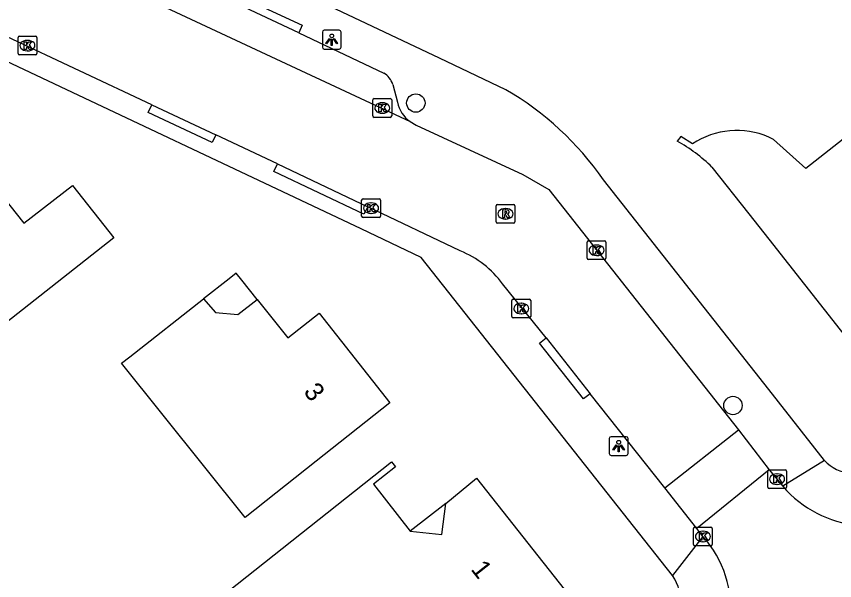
# Model space of a CAD drawing. Extents: x 159628 to 160723, y 388176 to 389416.
# Drawn here: x 159959.95 to 160003.51, y 388606.9 to 388636.95 of the extents above; entities that cross this region are included whole.
import ezdxf

# ---------------------------------------------------------------- set-up
doc = ezdxf.new("R2010")
doc.units = 0
for name, color, linetype in [('IMGEO_Boom', 7, 'Continuous'), ('IMGEO_Kolk', 7, 'Continuous'), ('IMGEO_Lichtpunt', 7, 'Continuous'), ('IMGEO_Pand', 7, 'Continuous'), ('IMGEO_Pand_nummerreeks', 7, 'Continuous'), ('IMGEO_Pand_overbouw', 7, 'Continuous'), ('IMGEO_Rijbaan_lokaal_open', 7, 'Continuous'), ('IMGEO_Rioolput', 7, 'Continuous'), ('IMGEO_Voetpad_open', 7, 'Continuous')]:
    doc.layers.add(name, color=color, linetype=linetype)

msp = doc.modelspace()

# ---------------------------------------------------------------- linework, layer by layer
at = {"layer": 'IMGEO_Boom'}
for centre in [(159981.213, 388632.329), (159998.095, 388616.223)]:
    msp.add_circle(centre, 0.489, dxfattribs=at)
at = {"layer": 'IMGEO_Kolk'}
for p, q in [((159960.038, 388634.963), (159960.038, 388635.815)), ((159960.113, 388635.889), (159960.965, 388635.889)), ((159960.526, 388635.669), (159960.551, 388635.669)), ((159961.039, 388635.815), (159961.039, 388634.963)), ((159960.549, 388635.109), (159960.524, 388635.109)), ((159960.965, 388634.889), (159960.113, 388634.889)), ((159978.927, 388631.64), (159978.927, 388632.492)), ((159979.002, 388632.566), (159979.854, 388632.566)), ((159979.928, 388632.492), (159979.928, 388631.64)), ((159979.415, 388632.346), (159979.44, 388632.346)), ((159979.854, 388631.566), (159979.002, 388631.566)), ((159979.438, 388631.786), (159979.413, 388631.786)), ((159978.404, 388627.233), (159979.256, 388627.233)), ((159978.329, 388626.307), (159978.329, 388627.159)), ((159978.817, 388627.013), (159978.842, 388627.013)), ((159979.33, 388627.159), (159979.33, 388626.307)), ((159978.84, 388626.453), (159978.815, 388626.453)), ((159979.256, 388626.233), (159978.404, 388626.233)), ((159990.334, 388624.064), (159990.334, 388624.916)), ((159990.409, 388624.99), (159991.261, 388624.99)), ((159990.822, 388624.77), (159990.847, 388624.77)), ((159991.335, 388624.916), (159991.335, 388624.064)), ((159990.845, 388624.21), (159990.82, 388624.21)), ((159991.261, 388623.99), (159990.409, 388623.99)), ((159986.326, 388620.96), (159986.326, 388621.812)), ((159986.401, 388621.886), (159987.253, 388621.886)), ((159986.814, 388621.666), (159986.839, 388621.666)), ((159987.327, 388621.812), (159987.327, 388620.96)), ((159987.253, 388620.886), (159986.401, 388620.886)), ((159986.837, 388621.106), (159986.812, 388621.106)), ((159999.943, 388611.873), (159999.943, 388612.725)), ((160000.018, 388612.799), (160000.87, 388612.799)), ((160000.431, 388612.579), (160000.456, 388612.579)), ((160000.944, 388612.725), (160000.944, 388611.873)), ((160000.454, 388612.019), (160000.429, 388612.019)), ((160000.87, 388611.799), (160000.018, 388611.799)), ((159995.994, 388608.825), (159995.994, 388609.677)), ((159996.069, 388609.751), (159996.921, 388609.751)), ((159996.482, 388609.531), (159996.507, 388609.531)), ((159996.995, 388609.677), (159996.995, 388608.825)), ((159996.505, 388608.971), (159996.48, 388608.971)), ((159996.921, 388608.751), (159996.069, 388608.751))]:
    msp.add_line(p, q, dxfattribs=at)
for points in [[(159960.038, 388634.963), (159960.038, 388635.815)], [(159960.113, 388635.889), (159960.965, 388635.889)], [(159960.359, 388635.589), (159960.482, 388635.589), (159960.482, 388635.438), (159960.612, 388635.589), (159960.776, 388635.589), (159960.63, 388635.438), (159960.783, 388635.189), (159960.631, 388635.189), (159960.546, 388635.353), (159960.482, 388635.286), (159960.482, 388635.189), (159960.359, 388635.189), (159960.359, 388635.589)], [(159961.039, 388635.815), (159961.039, 388634.963)], [(159960.965, 388634.889), (159960.113, 388634.889)], [(159978.927, 388631.64), (159978.927, 388632.492)], [(159979.002, 388632.566), (159979.854, 388632.566)], [(159979.928, 388632.492), (159979.928, 388631.64)], [(159979.248, 388632.266), (159979.371, 388632.266), (159979.371, 388632.115), (159979.501, 388632.266), (159979.665, 388632.266), (159979.519, 388632.115), (159979.672, 388631.866), (159979.52, 388631.866), (159979.435, 388632.03), (159979.371, 388631.963), (159979.371, 388631.866), (159979.248, 388631.866), (159979.248, 388632.266)], [(159979.854, 388631.566), (159979.002, 388631.566)], [(159978.404, 388627.233), (159979.256, 388627.233)], [(159978.329, 388626.307), (159978.329, 388627.159)], [(159978.65, 388626.933), (159978.773, 388626.933), (159978.773, 388626.782), (159978.903, 388626.933), (159979.067, 388626.933), (159978.921, 388626.782), (159979.074, 388626.533), (159978.922, 388626.533), (159978.837, 388626.697), (159978.773, 388626.63), (159978.773, 388626.533), (159978.65, 388626.533), (159978.65, 388626.933)], [(159979.33, 388627.159), (159979.33, 388626.307)], [(159979.256, 388626.233), (159978.404, 388626.233)], [(159990.334, 388624.064), (159990.334, 388624.916)], [(159990.409, 388624.99), (159991.261, 388624.99)], [(159990.655, 388624.69), (159990.778, 388624.69), (159990.778, 388624.539), (159990.908, 388624.69), (159991.072, 388624.69), (159990.926, 388624.539), (159991.079, 388624.29), (159990.927, 388624.29), (159990.842, 388624.454), (159990.778, 388624.387), (159990.778, 388624.29), (159990.655, 388624.29), (159990.655, 388624.69)], [(159991.335, 388624.916), (159991.335, 388624.064)], [(159991.261, 388623.99), (159990.409, 388623.99)], [(159986.326, 388620.96), (159986.326, 388621.812)], [(159986.401, 388621.886), (159987.253, 388621.886)], [(159986.647, 388621.586), (159986.77, 388621.586), (159986.77, 388621.435), (159986.9, 388621.586), (159987.064, 388621.586), (159986.918, 388621.435), (159987.071, 388621.186), (159986.919, 388621.186), (159986.834, 388621.35), (159986.77, 388621.283), (159986.77, 388621.186), (159986.647, 388621.186), (159986.647, 388621.586)], [(159987.327, 388621.812), (159987.327, 388620.96)], [(159987.253, 388620.886), (159986.401, 388620.886)], [(159999.943, 388611.873), (159999.943, 388612.725)], [(160000.018, 388612.799), (160000.87, 388612.799)], [(160000.264, 388612.499), (160000.387, 388612.499), (160000.387, 388612.348), (160000.517, 388612.499), (160000.681, 388612.499), (160000.535, 388612.348), (160000.688, 388612.099), (160000.536, 388612.099), (160000.451, 388612.263), (160000.387, 388612.196), (160000.387, 388612.099), (160000.264, 388612.099), (160000.264, 388612.499)], [(160000.944, 388612.725), (160000.944, 388611.873)], [(160000.87, 388611.799), (160000.018, 388611.799)], [(159995.994, 388608.825), (159995.994, 388609.677)], [(159996.069, 388609.751), (159996.921, 388609.751)], [(159996.315, 388609.451), (159996.438, 388609.451), (159996.438, 388609.3), (159996.568, 388609.451), (159996.732, 388609.451), (159996.586, 388609.3), (159996.739, 388609.051), (159996.587, 388609.051), (159996.502, 388609.215), (159996.438, 388609.148), (159996.438, 388609.051), (159996.315, 388609.051), (159996.315, 388609.451)], [(159996.995, 388609.677), (159996.995, 388608.825)], [(159996.921, 388608.751), (159996.069, 388608.751)]]:
    msp.add_lwpolyline(points, dxfattribs=at)
for centre, start, end in [((159960.115, 388635.813), 91.552, 178.448), ((159960.115, 388635.813), 91.552, 178.448), ((159960.963, 388635.813), 1.552, 88.448), ((159960.963, 388635.813), 1.552, 88.448), ((159960.115, 388634.965), 181.552, 268.448), ((159960.115, 388634.965), 181.552, 268.448), ((159960.963, 388634.965), 271.552, 358.448), ((159960.963, 388634.965), 271.552, 358.448), ((159979.004, 388632.49), 91.552, 178.448), ((159979.004, 388632.49), 91.552, 178.448), ((159979.852, 388632.49), 1.552, 88.448), ((159979.852, 388632.49), 1.552, 88.448), ((159979.004, 388631.642), 181.552, 268.448), ((159979.004, 388631.642), 181.552, 268.448), ((159979.852, 388631.642), 271.552, 358.448), ((159979.852, 388631.642), 271.552, 358.448), ((159978.406, 388627.157), 91.552, 178.448), ((159978.406, 388627.157), 91.552, 178.448), ((159979.254, 388627.157), 1.552, 88.448), ((159979.254, 388627.157), 1.552, 88.448), ((159978.406, 388626.309), 181.552, 268.448), ((159978.406, 388626.309), 181.552, 268.448), ((159979.254, 388626.309), 271.552, 358.448), ((159979.254, 388626.309), 271.552, 358.448), ((159990.411, 388624.914), 91.552, 178.448), ((159990.411, 388624.914), 91.552, 178.448), ((159991.259, 388624.914), 1.552, 88.448), ((159991.259, 388624.914), 1.552, 88.448), ((159990.411, 388624.066), 181.552, 268.448), ((159990.411, 388624.066), 181.552, 268.448), ((159991.259, 388624.066), 271.552, 358.448), ((159991.259, 388624.066), 271.552, 358.448), ((159986.403, 388621.81), 91.552, 178.448), ((159986.403, 388621.81), 91.552, 178.448), ((159987.251, 388621.81), 1.552, 88.448), ((159987.251, 388621.81), 1.552, 88.448), ((159986.403, 388620.962), 181.552, 268.448), ((159986.403, 388620.962), 181.552, 268.448), ((159987.251, 388620.962), 271.552, 358.448), ((159987.251, 388620.962), 271.552, 358.448), ((160000.02, 388612.723), 91.552, 178.448), ((160000.02, 388612.723), 91.552, 178.448), ((160000.868, 388612.723), 1.552, 88.448), ((160000.868, 388612.723), 1.552, 88.448), ((160000.02, 388611.875), 181.552, 268.448), ((160000.02, 388611.875), 181.552, 268.448), ((160000.868, 388611.875), 271.552, 358.448), ((160000.868, 388611.875), 271.552, 358.448), ((159996.071, 388609.675), 91.552, 178.448), ((159996.071, 388609.675), 91.552, 178.448), ((159996.919, 388609.675), 1.552, 88.448), ((159996.919, 388609.675), 1.552, 88.448), ((159996.071, 388608.827), 181.552, 268.448), ((159996.071, 388608.827), 181.552, 268.448), ((159996.919, 388608.827), 271.552, 358.448), ((159996.919, 388608.827), 271.552, 358.448)]:
    msp.add_arc(centre, 0.0765, start, end, dxfattribs=at)
for centre, major_axis, ratio, start_param, end_param in [((159960.525, 388635.389), (-0.387, 0.002), 0.722429, 4.712389, 7.853982), ((159960.55, 388635.389), (-0.39, 0.002), 0.717154, 1.570796, 4.712389), ((159979.414, 388632.066), (-0.387, 0.002), 0.722429, 4.712389, 7.853982), ((159979.439, 388632.066), (-0.39, 0.002), 0.717154, 1.570796, 4.712389), ((159978.816, 388626.733), (-0.387, 0.002), 0.722429, 4.712389, 7.853982), ((159978.841, 388626.733), (-0.39, 0.002), 0.717154, 1.570796, 4.712389), ((159990.821, 388624.49), (-0.387, 0.002), 0.722429, 4.712389, 7.853982), ((159990.846, 388624.49), (-0.39, 0.002), 0.717154, 1.570796, 4.712389), ((159986.813, 388621.386), (-0.387, 0.002), 0.722429, 4.712389, 7.853982), ((159986.838, 388621.386), (-0.39, 0.002), 0.717154, 1.570796, 4.712389), ((160000.43, 388612.299), (-0.387, 0.002), 0.722429, 4.712389, 7.853982), ((160000.455, 388612.299), (-0.39, 0.002), 0.717154, 1.570796, 4.712389), ((159996.481, 388609.251), (-0.387, 0.002), 0.722429, 4.712389, 7.853982), ((159996.506, 388609.251), (-0.39, 0.002), 0.717154, 1.570796, 4.712389)]:
    msp.add_ellipse(centre, major_axis=major_axis, ratio=ratio, start_param=start_param, end_param=end_param, dxfattribs=at)
at = {"layer": 'IMGEO_Lichtpunt'}
for p, q in [((159976.238, 388636.108), (159976.238, 388635.301)), ((159976.238, 388636.108), (159976.238, 388635.301)), ((159977.14, 388636.203), (159976.332, 388636.203)), ((159977.14, 388636.203), (159976.332, 388636.203)), ((159977.234, 388635.301), (159977.234, 388636.108)), ((159977.234, 388635.301), (159977.234, 388636.108)), ((159976.332, 388635.207), (159977.14, 388635.207)), ((159976.332, 388635.207), (159977.14, 388635.207)), ((159991.512, 388614.465), (159991.512, 388613.658)), ((159991.512, 388614.465), (159991.512, 388613.658)), ((159992.414, 388614.56), (159991.606, 388614.56)), ((159992.414, 388614.56), (159991.606, 388614.56)), ((159992.508, 388613.658), (159992.508, 388614.465)), ((159992.508, 388613.658), (159992.508, 388614.465)), ((159991.606, 388613.564), (159992.414, 388613.564)), ((159991.606, 388613.564), (159992.414, 388613.564))]:
    msp.add_line(p, q, dxfattribs=at)
for points in [[(159976.612, 388635.772), (159976.651, 388635.744), (159976.463, 388635.482), (159976.425, 388635.509), (159976.612, 388635.772)], [(159976.714, 388635.724), (159976.761, 388635.724), (159976.761, 388635.402), (159976.714, 388635.402), (159976.714, 388635.724)], [(159976.824, 388635.744), (159976.862, 388635.771), (159977.049, 388635.509), (159977.01, 388635.481), (159976.824, 388635.744)], [(159991.886, 388614.129), (159991.925, 388614.101), (159991.737, 388613.839), (159991.699, 388613.866), (159991.886, 388614.129)], [(159991.988, 388614.081), (159992.035, 388614.081), (159992.035, 388613.759), (159991.988, 388613.759), (159991.988, 388614.081)], [(159992.098, 388614.101), (159992.136, 388614.128), (159992.323, 388613.866), (159992.284, 388613.838), (159992.098, 388614.101)]]:
    msp.add_lwpolyline(points, dxfattribs=at)
for centre in [(159976.737, 388635.906), (159992.011, 388614.263)]:
    msp.add_circle(centre, 0.0994, dxfattribs=at)
for centre, start, end in [((159976.332, 388636.108), 90, 180), ((159976.332, 388636.108), 90, 180), ((159977.14, 388636.108), 0, 90), ((159977.14, 388636.108), 0, 90), ((159976.332, 388635.301), 180, 270), ((159976.332, 388635.301), 180, 270), ((159977.14, 388635.301), 270, 0), ((159977.14, 388635.301), 270, 360), ((159991.606, 388614.465), 90, 180), ((159991.606, 388614.465), 90, 180), ((159992.414, 388614.465), 0, 90), ((159992.414, 388614.465), 0, 90), ((159991.606, 388613.658), 180, 270), ((159991.606, 388613.658), 180, 270), ((159992.414, 388613.658), 270, 0), ((159992.414, 388613.658), 270, 360)]:
    msp.add_arc(centre, 0.0946, start, end, dxfattribs=at)
at = {"layer": 'IMGEO_Pand'}
for points in [[(160006.35, 388632.29), (160001.98, 388628.837), (160000.259, 388630.396), (160000, 388630.519)], [(159995.943, 388630.158), (159995.312, 388630.544), (159995.123, 388630.297)], [(159996.977, 388628.914), (159998.934, 388626.43), (160000, 388625.078), (160004.849, 388618.927)], [(159959.266, 388627.3), (159960.348, 388625.938), (159962.942, 388627.943), (159965.142, 388625.158), (159954.57, 388616.83), (159948.766, 388624.226)], [(159965.554, 388618.482), (159965.985, 388618.82), (159969.918, 388621.906), (159970.55, 388621.181), (159971.742, 388621.064), (159972.765, 388621.862), (159974.401, 388619.82), (159976.062, 388621.142), (159979.827, 388616.37), (159975.909, 388613.265), (159972.123, 388610.264), (159965.554, 388618.482)], [(159977.152, 388604.649), (159974.803, 388602.785), (159974.431, 388603.254), (159971.308, 388600.776), (159969.731, 388599.525), (159966.996, 388602.972), (159971.696, 388606.701), (159979.927, 388613.231), (159980.13, 388612.965), (159978.952, 388612.041), (159980.918, 388609.537), (159982.606, 388609.353), (159982.809, 388611.002), (159984.451, 388612.35), (159989.108, 388606.451), (159980.88, 388599.95), (159977.152, 388604.649)]]:
    msp.add_lwpolyline(points, dxfattribs=at)
for centre, radius, start, end in [((159998.304, 388626.597), 4.273, 66.622, 123.5478), ((159991.186, 388623.085), 8.216, 45.1871, 61.3704)]:
    msp.add_arc(centre, radius, start, end, dxfattribs=at)
at = {"layer": 'IMGEO_Pand_overbouw'}
for points in [[(159969.918, 388621.906), (159970.55, 388621.181), (159971.742, 388621.064), (159972.765, 388621.862), (159971.959, 388622.898), (159971.655, 388623.275), (159971.271, 388622.975)], [(159982.809, 388611.002), (159980.918, 388609.537), (159982.606, 388609.353)]]:
    msp.add_lwpolyline(points, close=True, dxfattribs=at)
at = {"layer": 'IMGEO_Rijbaan_lokaal_open'}
for points in [[(159961.021, 388640.652), (159980.906, 388631.34)], [(159967.155, 388632.23), (159959.462, 388635.859)], [(159967.155, 388632.23), (159970.561, 388630.635)], [(159980.906, 388631.34), (159981.225, 388631.153), (159986.905, 388628.53), (159988.285, 388627.721), (159998.383, 388614.922)], [(159973.844, 388629.101), (159970.561, 388630.635)], [(159973.844, 388629.101), (159978.653, 388626.808)], [(159983.578, 388624.453), (159978.653, 388626.808)], [(159988.152, 388619.823), (159985.833, 388622.694)], [(159988.152, 388619.823), (159990.497, 388616.852)], [(159994.461, 388611.83), (159990.497, 388616.852)], [(159994.461, 388611.83), (159998.383, 388614.922)], [(159998.383, 388614.922), (160000.014, 388612.793)], [(160000.014, 388612.793), (159996.163, 388609.674)], [(160000.014, 388612.793), (160000.751, 388611.921)], [(159996.163, 388609.674), (159994.461, 388611.83)], [(159996.498, 388609.249), (159996.163, 388609.674)]]:
    msp.add_lwpolyline(points, dxfattribs=at)
for centre, radius, start, end in [((159981.682, 388619.697), 5.12, 35.8263, 68.2621), ((160005.342, 388615.86), 6.049, 220.628, 307.1905), ((159991.979, 388605.263), 6.026, 308.5952, 41.4153)]:
    msp.add_arc(centre, radius, start, end, dxfattribs=at)
at = {"layer": 'IMGEO_Rioolput'}
for p, q in [((159985.487, 388626.008), (159985.487, 388626.86)), ((159985.562, 388626.934), (159986.414, 388626.934)), ((159986.488, 388626.86), (159986.488, 388626.008)), ((159985.975, 388626.714), (159986, 388626.714)), ((159986.414, 388625.934), (159985.562, 388625.934)), ((159985.998, 388626.154), (159985.973, 388626.154))]:
    msp.add_line(p, q, dxfattribs=at)
for points in [[(159985.487, 388626.008), (159985.487, 388626.86)], [(159985.562, 388626.934), (159986.414, 388626.934)], [(159986.488, 388626.86), (159986.488, 388626.008)], [(159986.076, 388626.632), (159985.824, 388626.634), (159985.824, 388626.234)], [(159985.824, 388626.234), (159985.948, 388626.234), (159985.948, 388626.396), (159985.959, 388626.396)], [(159986.002, 388626.553), (159985.948, 388626.553), (159985.948, 388626.472)], [(159985.948, 388626.472), (159986, 388626.472)], [(159986.006, 388626.367), (159986.077, 388626.234), (159986.217, 388626.234), (159986.152, 388626.36)], [(159986.414, 388625.934), (159985.562, 388625.934)]]:
    msp.add_lwpolyline(points, dxfattribs=at)
for centre, radius, start, end in [((159985.564, 388626.858), 0.0765, 91.552, 178.448), ((159985.564, 388626.858), 0.0765, 91.552, 178.448), ((159986.412, 388626.858), 0.0765, 1.552, 88.448), ((159986.412, 388626.858), 0.0765, 1.552, 88.448), ((159985.958, 388626.343), 0.0533, 26.0293, 88.6989), ((159985.984, 388626.661), 0.19, 274.7715, 282.9687), ((159986.008, 388626.457), 0.0964, 77.0061, 93.1865), ((159986.022, 388626.514), 0.0378, 276.6634, 79.6772), ((159986.075, 388626.522), 0.109, 350.3612, 89.416), ((159986.073, 388626.522), 0.112, 277.5842, 350.9817), ((159986.057, 388626.307), 0.108, 29.5134, 73.7905), ((159985.564, 388626.01), 0.0765, 181.552, 268.448), ((159985.564, 388626.01), 0.0765, 181.552, 268.448), ((159986.412, 388626.01), 0.0765, 271.552, 358.448), ((159986.412, 388626.01), 0.0765, 271.552, 358.448)]:
    msp.add_arc(centre, radius, start, end, dxfattribs=at)
for centre, major_axis, ratio, start_param, end_param in [((159985.974, 388626.434), (-0.387, 0.002), 0.722429, 4.712389, 7.853982), ((159985.999, 388626.434), (-0.39, 0.002), 0.717154, 1.570796, 4.712389)]:
    msp.add_ellipse(centre, major_axis=major_axis, ratio=ratio, start_param=start_param, end_param=end_param, dxfattribs=at)
at = {"layer": 'IMGEO_Voetpad_open'}
for points in [[(159986.01, 388633.035), (159982.465, 388634.72), (159961.709, 388644.549)], [(159971.546, 388637.677), (159971.739, 388638.078), (159975.157, 388636.481), (159974.977, 388636.06)], [(159974.977, 388636.06), (159971.546, 388637.677)], [(159974.977, 388636.06), (159979.509, 388633.923)], [(159994.869, 388607.162), (159981.506, 388624.102), (159978.304, 388625.626), (159958.752, 388634.855)], [(159979.983, 388633.323), (159980.232, 388632.374)], [(159970.561, 388630.635), (159970.367, 388630.223), (159966.964, 388631.825), (159967.155, 388632.23)], [(159978.653, 388626.808), (159978.45, 388626.414), (159973.656, 388628.679), (159973.844, 388629.101)], [(160002.97, 388613.298), (160000, 388617.069), (159991.198, 388628.245)], [(159990.497, 388616.852), (159990.147, 388616.581), (159987.791, 388619.541), (159988.152, 388619.823)], [(160002.97, 388613.298), (160000.751, 388611.921)], [(159996.498, 388609.249), (159994.869, 388607.162)]]:
    msp.add_lwpolyline(points, dxfattribs=at)
for centre, radius, start, end in [((159978.969, 388633.009), 1.062, 17.2048, 59.4127), ((159977.913, 388619.061), 16.15, 34.6568, 59.9116), ((159981.946, 388632.754), 1.755, 192.5149, 233.6807), ((160004.471, 388614.632), 2.008, 221.6256, 310.9407), ((159993.158, 388605.877), 2.14, 303.4112, 36.8965)]:
    msp.add_arc(centre, radius, start, end, dxfattribs=at)

# ---------------------------------------------------------------- texts
at = {"layer": 'IMGEO_Pand_nummerreeks'}
for s, rotation, p in [('3', 308.2726, (159975.199, 388616.941)), ('1', 308.2906, (159984.105, 388607.495))]:
    msp.add_text(s, height=1, rotation=rotation, dxfattribs=at).set_placement(p)

doc.saveas('drawing.dxf')
